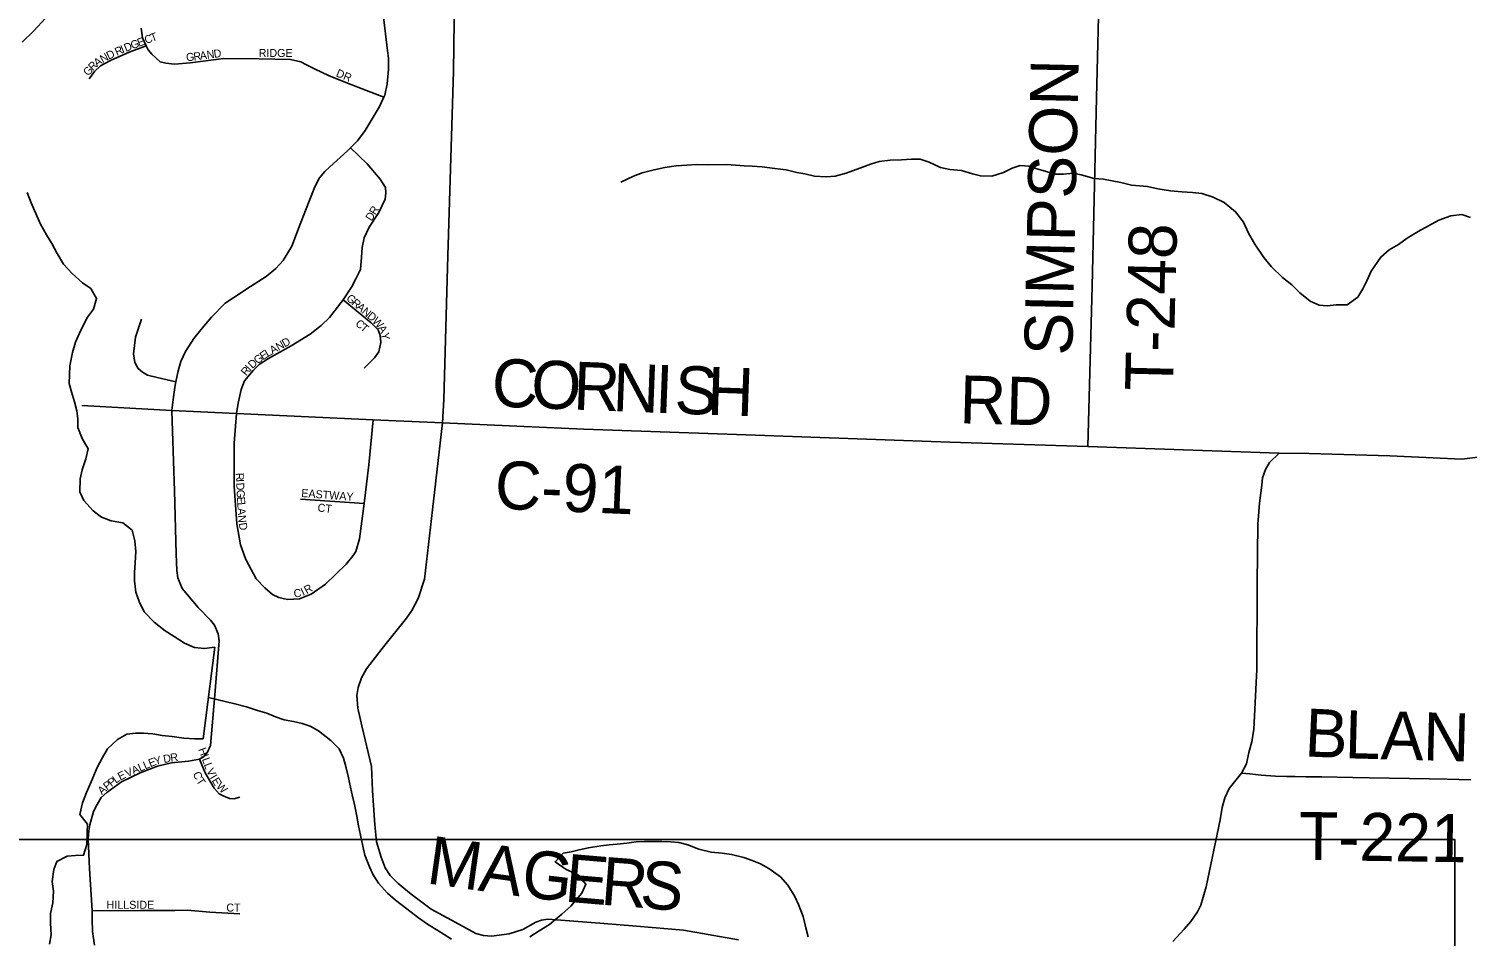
# Model space of a CAD drawing. Extents: x 1759416 to 2214760, y 252598 to 1116833.
# Drawn here: x 2011247 to 2020235, y 879811 to 885483 of the extents above; entities that cross this region are included whole.
import ezdxf

# ---------------------------------------------------------------- set-up
doc = ezdxf.new("R2010")
doc.units = 0
for name, color, linetype in [('GM_X_County_Road', 7, 'Continuous'), ('GM_X_County_Road_Text', 7, 'Continuous'), ('GM_X_County_Subdivision', 7, 'Continuous'), ('GM_X_County_Subdivision_Text', 7, 'Continuous'), ('GM_X_Major_Lake', 7, 'Continuous'), ('GM_X_Minor_River', 7, 'Continuous'), ('GM_X_Township_Road', 7, 'Continuous'), ('GM_X_Township_Road_Text', 7, 'Continuous'), ('GM_X_Township_Subdivision', 7, 'Continuous'), ('GM_X_Township_Subdivision_Text', 7, 'Continuous'), ('SC_Scratch1', 7, 'Continuous')]:
    doc.layers.add(name, color=color, linetype=linetype)

msp = doc.modelspace()

# ---------------------------------------------------------------- linework, layer by layer
at = {"layer": 'GM_X_County_Road'}
for points in [[(2013409.9, 880508.4), (2013409.8, 880509.6), (2013407.5, 880535.4), (2013395.7, 880721.7), (2013387.9, 880872), (2013328.1, 881126.5), (2013304.2, 881236.7), (2013296.3, 881314.8), (2013304.3, 881364.9), (2013326.4, 881425), (2013356.5, 881481), (2013454.6, 881609.2), (2013606.9, 881799.3), (2013641, 881847.4), (2013681.1, 881921.4), (2013719.2, 882041.6), (2013769.7, 882476.3), (2013832.3, 883019.1), (2013840.5, 883165.4), (2013865.4, 884062.9), (2013900.7, 885216.8), (2013909.3, 885843.9)], [(2012141.5, 883096.3), (2012544.1, 883078.3), (2013398.5, 883039.3), (2013832.3, 883019.1)], [(2013832.3, 883019.1), (2014715, 882979.1), (2015730.3, 882945), (2017002, 882898.3), (2017865.1, 882871.3), (2019061, 882830.6)], [(2018395.4, 879778.2), (2018465.5, 879854.2), (2018507.6, 879902.2), (2018549.7, 879962.3), (2018569.8, 880004.3), (2018603.9, 880118.5), (2018690.4, 880539.1), (2018704.5, 880615.2), (2018720.5, 880675.3), (2018746.6, 880733.3), (2018824.1, 880830.2), (2018856.7, 880887.4), (2018870.9, 880959.6), (2018889, 881025.7), (2018901.1, 881105.8), (2018919.5, 881478.4), (2018922, 882015.3), (2018926.4, 882386), (2018936.6, 882518.2), (2018952.7, 882630.4), (2018956.8, 882676.4), (2018974.8, 882728.5), (2018998.9, 882772.5), (2019061, 882830.6), (2019247.1, 882828.3), (2019751.3, 882813.7), (2020201.6, 882793.1), (2020317.6, 882807)], [(2015682, 879787.4), (2015337.9, 879847.9), (2015043.7, 879874.4), (2014815.6, 879892.6), (2014489.5, 879917.1), (2014451.4, 879911.1), (2014415.4, 879899.1), (2014333.3, 879853.1), (2014249.2, 879825.2), (2014139.1, 879811.3), (2014089.1, 879815.4), (2014041.1, 879827.4), (2013911.1, 879897.7), (2013761.1, 879980), (2013637.1, 880074.3), (2013555.2, 880140.5), (2013505.2, 880190.7), (2013473.2, 880238.8), (2013449.3, 880304.9), (2013419.4, 880401.1), (2013409.9, 880508.4)]]:
    msp.add_lwpolyline(points, dxfattribs=at)
at = {"layer": 'GM_X_County_Subdivision'}
msp.add_lwpolyline([(2013461.7, 885572.8), (2013484.9, 885380.5), (2013495.4, 885296.4), (2013493.8, 885228.3), (2013486.4, 885138.1), (2013472.8, 885067.8), (2013466.6, 885054.6), (2013437.2, 884991.5), (2013350, 884846.7), (2013300.4, 884782.3), (2013257.6, 884739), (2013238.7, 884719.8), (2013129.2, 884619), (2013097.4, 884590.8), (2013063.6, 884550.5), (2013033.9, 884494.2), (2012998.4, 884405.8), (2012943.2, 884261.2), (2012890, 884124.6), (2012836.5, 884034.2), (2012790.8, 883983.8), (2012731, 883933.3), (2012633.3, 883870.6), (2012527.6, 883803.9), (2012473.7, 883767.5), (2012388.2, 883680.8), (2012340.5, 883624.5), (2012278.9, 883546), (2012227.3, 883465.5), (2012197.7, 883403.2), (2012180, 883345), (2012166.6, 883275.8), (2012162.6, 883254.7), (2012151, 883182.5), (2012141.5, 883096.3), (2012143.9, 883030.2), (2012158.6, 882595.4), (2012169, 882200.8), (2012171.7, 882096.6), (2012178, 882050.5), (2012206.4, 881984.6), (2012305.3, 881864.9), (2012381.9, 881785.2), (2012408.1, 881755.3), (2012430.4, 881701.4), (2012436.7, 881657.3), (2012408.8, 881318.5), (2012382.7, 881003.7), (2012362.9, 880961.6), (2012339.1, 880931.3), (2012312.9, 880916.8), (2012245.1, 880904.8), (2012139.1, 880894.1), (2012051.1, 880873.6), (2011943.3, 880832.9), (2011827.5, 880776.1), (2011733.8, 880709.4), (2011699.9, 880677.1), (2011674.2, 880634.9), (2011652.4, 880590.7), (2011628.9, 880506.4), (2011623.1, 880470.3), (2011617.4, 880420.2), (2011626.6, 880231.9), (2011642.2, 879971.5), (2011644, 879916.3), (2011646.3, 879840.2), (2011657.6, 879755.1)], dxfattribs=at)
at = {"layer": 'GM_X_Major_Lake'}
for points in [[(2011205.5, 885397.8), (2011279.3, 885470.2), (2011351.1, 885548.6)], [(2012409.6, 881618.1), (2012345.5, 881609.9), (2012283.4, 881615.7), (2012219.2, 881641.5), (2012155, 881683.4), (2012098.8, 881719.3), (2012030.5, 881773.2), (2011968.1, 881839.1), (2011937.8, 881903.1), (2011915.6, 881961.2), (2011907.3, 882031.3), (2011907.1, 882083.4), (2011910.9, 882145.5), (2011916.6, 882215.7), (2011910.4, 882281.8), (2011894.1, 882347.9), (2011835.8, 882393.8), (2011761.7, 882407.5), (2011701.5, 882429.4), (2011649.3, 882469.3), (2011591, 882533.2), (2011566.7, 882589.2), (2011568.4, 882669.4), (2011580.2, 882725.6), (2011604, 882793.8), (2011617.8, 882858), (2011581.5, 882922), (2011553.2, 882990), (2011552.9, 883044.1), (2011546.8, 883094.2), (2011532.5, 883150.3), (2011514.3, 883212.3), (2011500, 883266.4), (2011501.8, 883320.5), (2011503.6, 883376.7), (2011519.3, 883458.9), (2011539.1, 883523.1), (2011572.9, 883599.3), (2011614.6, 883679.7), (2011652.5, 883729.9), (2011670.3, 883796.1), (2011634, 883858.1), (2011583.8, 883894), (2011517.4, 883951.9), (2011465.1, 884011.8), (2011424.8, 884077.8), (2011390.6, 884139.8), (2011358.3, 884193.8), (2011320, 884261.8), (2011297.8, 884313.9), (2011261.4, 884393.9), (2011237.1, 884460)], [(2012337.7, 881044.7), (2012409.6, 881618.1)], [(2011377.2, 879760.8), (2011387, 879819), (2011382.7, 879893.1), (2011382.5, 879953.2), (2011398.3, 880019.4), (2011402, 880091.6), (2011393.8, 880153.7), (2011403.5, 880227.8), (2011423.3, 880278), (2011487.3, 880310.3), (2011539.4, 880314.5), (2011589.4, 880316.7), (2011609.2, 880384.9), (2011612.9, 880461), (2011614.7, 880511.2), (2011566.4, 880571.1), (2011582.1, 880645.3), (2011607.9, 880709.5), (2011637.7, 880775.8), (2011673.4, 880866.1), (2011707.2, 880928.3), (2011739.1, 880982.5), (2011800.9, 881040.9), (2011858.9, 881073.1), (2011913, 881079.3), (2011963, 881079.5), (2012023.1, 881075.7), (2012081.2, 881065.9), (2012143.4, 881058.1), (2012215.5, 881048.3), (2012285.6, 881044.5), (2012337.7, 881044.7)]]:
    msp.add_lwpolyline(points, dxfattribs=at)
at = {"layer": 'GM_X_Minor_River'}
for points in [[(2016285.8, 884561.3), (2016229.7, 884557.1), (2016157.6, 884560.9), (2016095.5, 884576.7), (2016045.4, 884584.6), (2015979.2, 884600.4), (2015909.1, 884610.2), (2015828.9, 884619.9), (2015766.8, 884623.7), (2015716.8, 884625.5), (2015608.6, 884633.2), (2015486.4, 884632.8), (2015418.3, 884634.5), (2015358.2, 884630.3), (2015292.2, 884626.1), (2015222.1, 884615.8), (2015154.1, 884601.6), (2015080, 884581.3), (2015026, 884561.1), (2014946.1, 884524.7)], [(2020256.3, 884302.2), (2020202.1, 884322), (2020132.1, 884313.8), (2020058.1, 884285.5), (2019994.1, 884251.2), (2019928.2, 884214.9), (2019860.2, 884174.6), (2019806.3, 884134.3), (2019748.4, 884100), (2019694.5, 884055.8), (2019634.7, 883967.4), (2019606.9, 883907.2), (2019583.1, 883857), (2019551.2, 883804.8), (2019485.3, 883756.4), (2019417.2, 883756.2), (2019359.2, 883750), (2019309.1, 883755.9), (2019252.9, 883779.7), (2019188.6, 883831.6), (2019138.3, 883881.5), (2019080.1, 883927.4), (2019011.7, 883995.4), (2018963.5, 884053.3), (2018907.1, 884135.3), (2018868.7, 884205.3), (2018836.4, 884273.3), (2018788.1, 884339.3), (2018715.8, 884397.2), (2018647.6, 884431), (2018577.4, 884452.8), (2018519.3, 884458.7), (2018451.2, 884462.4), (2018381.1, 884470.2), (2018302.9, 884482), (2018236.8, 884495.8), (2018186.7, 884501.6), (2018136.6, 884505.5), (2018070.4, 884521.3), (2018016.3, 884533.1), (2017962.2, 884542.9), (2017904.1, 884546.8), (2017823.9, 884570.5), (2017769.8, 884580.4), (2017711.7, 884574.2), (2017655.7, 884574), (2017597.5, 884591.8), (2017545.4, 884607.7), (2017495.2, 884623.5), (2017441.1, 884627.4), (2017391.1, 884611.2), (2017337.2, 884584.9), (2017265.2, 884560.6), (2017193, 884562.4), (2017142.9, 884576.2), (2017074.8, 884596.1), (2017002.6, 884603.8), (2016944.5, 884615.7), (2016872.3, 884649.5), (2016816.1, 884667.3), (2016762, 884667.2), (2016700, 884662.9), (2016629.9, 884660.7), (2016559.8, 884652.4), (2016505.8, 884636.2), (2016439.8, 884612), (2016353.8, 884579.6), (2016285.8, 884561.3)], [(2012843.9, 881162.7), (2012787.8, 881182.5), (2012735.6, 881204.4), (2012675.5, 881222.2), (2012607.3, 881244), (2012535.1, 881263.8), (2012370, 881302.8)], [(2013888.6, 879791.4), (2013820.4, 879835.3), (2013738, 879887.1), (2013681.8, 879925), (2013609.5, 879980.9), (2013539.2, 880036.8), (2013489, 880080.7), (2013432.6, 880142.6), (2013398.4, 880194.6), (2013376.2, 880244.6), (2013347.9, 880316.7), (2013333.6, 880372.7), (2013319.3, 880442.8), (2013307.1, 880500.9), (2013296.9, 880561), (2013282.6, 880633.1), (2013268.3, 880695.2), (2013254, 880761.3), (2013243.8, 880811.3), (2013229.6, 880863.4), (2013213.4, 880923.4), (2013187.1, 880981.5), (2013134.8, 881033.4), (2013056.5, 881095.3), (2013006.3, 881123.2), (2012956.2, 881141), (2012902, 881152.8), (2012843.9, 881162.7)], [(2016117.7, 879807), (2016103.4, 879863.1), (2016085.1, 879933.2), (2016056.8, 880009.2), (2016034.6, 880059.3), (2015990.3, 880129.2), (2015944, 880181.2), (2015871.7, 880233.1), (2015819.5, 880262.9), (2015767.3, 880284.8), (2015715.2, 880302.7), (2015639, 880322.5), (2015578.9, 880330.3), (2015510.8, 880336), (2015434.6, 880355.8), (2015364.4, 880381.6), (2015308.3, 880395.5), (2015256.2, 880401.3), (2015202.1, 880403.1), (2015094, 880402.8), (2015041.9, 880400.6), (2014983.9, 880392.4), (2014923.8, 880386.2), (2014873.7, 880382), (2014821.7, 880375.8), (2014743.6, 880363.5), (2014685.6, 880351.3), (2014635.6, 880339.1), (2014585.5, 880328.9), (2014535.7, 880276.6), (2014605.9, 880228.8), (2014676.2, 880196.9), (2014728.5, 880137), (2014702.6, 880080.8), (2014634.9, 879998.4), (2014577, 879948.1), (2014501.1, 879883.7), (2014437.2, 879845.4), (2014377.2, 879807.1)]]:
    msp.add_lwpolyline(points, dxfattribs=at)
at = {"layer": 'GM_X_Township_Road'}
for points in [[(2017865.1, 882871.3), (2017890.9, 883873.3), (2017917.7, 885051.7), (2017956.4, 886574.9), (2017989.9, 888044.9)], [(2011579.6, 883127.2), (2011692, 883121.1), (2011692, 883121.1)], [(2011692, 883121.1), (2012141.5, 883096.3)], [(2018824.1, 880830.2), (2018876.3, 880825.2), (2018948, 880818.4), (2019036.2, 880811.9), (2019108.2, 880809.3), (2019160.6, 880808.5), (2019226, 880807.7), (2019327.4, 880807.1), (2019520.2, 880803.4), (2019624.9, 880800.4), (2019998.5, 880794.5), (2020110, 880792.5), (2020257.5, 880787.6)]]:
    msp.add_lwpolyline(points, dxfattribs=at)
at = {"layer": 'GM_X_Township_Subdivision'}
for points in [[(2013466.6, 885054.6), (2013357.5, 885095.9), (2013237.7, 885143), (2013120, 885190.1), (2013036.3, 885230.9), (2012982.4, 885257.4), (2012946.5, 885275.7), (2012882.6, 885290.3), (2012686.5, 885293.9), (2012466.3, 885295.8), (2012255.9, 885269.5), (2012157.7, 885262.3), (2012103.7, 885266.7), (2012067.7, 885275.1), (2012016.1, 885323.6), (2011992.3, 885351.8), (2011980.4, 885376.8), (2011956.9, 885426.3), (2011949.4, 885486.5)], [(2011624.5, 885168.6), (2011656.9, 885216.4), (2011695.2, 885250.1), (2011757.5, 885283.7), (2011874.1, 885336.8), (2011980.4, 885376.8)], [(2012544.1, 883078.3), (2012554.7, 883143.1), (2012573.4, 883227.1), (2012595.8, 883281), (2012648.4, 883346.7), (2012686.8, 883384.5), (2012745.1, 883422), (2012885.9, 883501), (2013004.6, 883574.1), (2013073.1, 883627.6), (2013125.6, 883677.3), (2013210.6, 883788.8), (2013263.3, 883868.5), (2013291.7, 883920.3), (2013320.2, 883978.2), (2013326.8, 884054.3), (2013329.3, 884114.4), (2013341.9, 884176.4), (2013374.4, 884242.2), (2013435.2, 884333.9), (2013474, 884417.7), (2013478.3, 884457.7), (2013476.6, 884489.8), (2013443, 884542.2), (2013361.7, 884639), (2013257.6, 884739)], [(2013343.2, 883360.9), (2013407.8, 883426.5), (2013434.1, 883464.3), (2013446.6, 883522.3), (2013442.9, 883564.4), (2013429.2, 883600.6), (2013385.5, 883645.1), (2013210.6, 883788.8)], [(2012166.6, 883275.8), (2012049.5, 883303.6), (2011989.6, 883318.1), (2011957.7, 883336.5), (2011929.9, 883358.7), (2011910.1, 883397), (2011900.6, 883451.2), (2011913.5, 883555.2), (2011952.4, 883667.1)], [(2012544.1, 883078.3), (2012530.6, 882892.9), (2012530.4, 882624.4), (2012546.4, 882387.8), (2012569.4, 882257.4), (2012602.7, 882164.9), (2012667.7, 882044.2), (2012721.3, 881987.6), (2012771, 881947.2), (2012808.9, 881926.8), (2012862.8, 881916.3), (2012939, 881919.7), (2013011.3, 881949.1), (2013101.8, 882010.5), (2013231, 882135.6), (2013273.5, 882189.4), (2013291.7, 882215.3), (2013314.4, 882295.2), (2013342.2, 882515.4), (2013372.2, 882757.6), (2013398.5, 883039.3)], [(2012944.1, 882542.8), (2013342.2, 882515.4)], [(2012566.9, 880680.2), (2012528.9, 880670), (2012500.9, 880671.8), (2012460.7, 880687.6), (2012436.6, 880701.5), (2012406.3, 880735.4), (2012349.7, 880831.2), (2012312.9, 880916.8)], [(2011642.2, 879971.5), (2011758.4, 879970.1), (2011944.6, 879971.2), (2012158.8, 879972.5), (2012238.9, 879972.9), (2012379.1, 879961.8), (2012565.4, 879950.8)]]:
    msp.add_lwpolyline(points, dxfattribs=at)
at = {"layer": 'SC_Scratch1'}
msp.add_lwpolyline([(1984253.2, 880416.3), (2020157.2, 880416.3), (2020157.2, 844512.3), (1984253.2, 844512.3)], close=True, dxfattribs=at)

# ---------------------------------------------------------------- texts
at = {"layer": 'GM_X_County_Road_Text'}
for s, rotation, p in [('C', 357.79035, (2014136, 883122.4)), ('O', 357.78944, (2014382.2, 883112.9)), ('R', 357.79035, (2014646, 883102.7)), ('N', 357.78944, (2014892.2, 883093.2)), ('I', 357.7905, (2015156, 883083.1)), ('S', 357.78896, (2015279.1, 883078.3)), ('H', 357.94893, (2015482.3, 883070.5)), ('RD', 358.51749, (2017060.5, 883016.8)), ('C-91', 357.60581, (2014154.9, 882483.8)), ('M', 351.95761, (2013725.6, 880142.5)), ('A', 352.03801, (2014048.5, 880096.9)), ('G', 353.3518, (2014317.4, 880059.4)), ('E', 355.13416, (2014589.7, 880027.8)), ('R', 355.54038, (2014815.6, 880008.6)), ('S', 355.07142, (2015060.6, 879989.5))]:
    msp.add_text(s, height=300, rotation=rotation, dxfattribs=at).set_placement(p)
at = {"layer": 'GM_X_County_Subdivision_Text'}
for s, rotation, p in [('E', 22.42025, (2012006.7, 880866)), ('Y', 15.08066, (2012037.7, 880878.9)), ('D', 10.6841, (2012092.1, 880892.8)), ('R', 7.9927, (2012134.7, 880900.8)), ('E', 26.87046, (2011818.6, 880782.6)), ('V', 23.25024, (2011861.3, 880803.5)), ('A', 23.25024, (2011901.8, 880820.9)), ('L', 23.25239, (2011942.2, 880838.3)), ('L', 23.22729, (2011974.5, 880852.2)), ('A', 42.23252, (2011704.4, 880691.8)), ('P', 38.24163, (2011736.3, 880720.8)), ('P', 36.99557, (2011763.7, 880742.4)), ('L', 35.09944, (2011791.4, 880763.4))]:
    msp.add_text(s, height=50, rotation=rotation, dxfattribs=at).set_placement(p)
at = {"layer": 'GM_X_Township_Road_Text'}
for s, rotation, p in [('SIMPSON', 88.73058, (2017766.7, 883438.2)), ('T-248', 88.59675, (2018396.4, 883216.1)), ('B', 357.30599, (2019215, 880935.3)), ('L', 358.45937, (2019467.7, 880923.4)), ('A', 358.5043, (2019692.3, 880917.4)), ('N', 358.50263, (2019956.2, 880910.5)), ('T-221', 359.15807, (2019181.4, 880288.2))]:
    msp.add_text(s, height=300, rotation=rotation, dxfattribs=at).set_placement(p)
at = {"layer": 'GM_X_Township_Subdivision_Text'}
for s, rotation, p in [('E', 20.54325, (2011935.2, 885369.3)), ('C', 20.5629, (2011980.6, 885386.3)), ('T', 20.54325, (2012017.6, 885400.2)), ('N', 29.3518, (2011708.7, 885267.3)), ('D', 25.39192, (2011746.2, 885288.5)), ('R', 23.90331, (2011797.7, 885312.7)), ('I', 23.88707, (2011833.9, 885328.7)), ('D', 22.02465, (2011853.6, 885337.4)), ('G', 20.64047, (2011894.1, 885353.8)), ('G', 3.84896, (2012231.6, 885279.9)), ('R', 7.40272, (2012278.9, 885283.1)), ('A', 7.76914, (2012318.5, 885288.3)), ('N', 7.76221, (2012362.1, 885294.2)), ('D', 7.7821, (2012405.7, 885300.2)), ('RIDGE', 0.00001, (2012683.9, 885306.2)), ('G', 51.17972, (2011620.3, 885183.6)), ('R', 44.10697, (2011646.8, 885216.7)), ('A', 34.79328, (2011673.6, 885242.9)), ('DR', 337.62245, (2013162.7, 885186.7)), ('R', 59.21274, (2013413.3, 884315.2)), ('D', 57.55898, (2013388.8, 884276.8)), ('G', 319.82782, (2013226.7, 883790.5)), ('R', 319.83067, (2013260.3, 883762.1)), ('A', 319.82782, (2013290.6, 883736.5)), ('N', 319.82782, (2013324.2, 883708.2)), ('D', 319.37738, (2013357.7, 883679.9)), ('C', 317.81781, (2013283.6, 883634.1)), ('T', 319.68976, (2013314.3, 883606.4)), ('W', 312.39582, (2013390, 883652.3)), ('A', 300.53647, (2013426.9, 883612.3)), ('N', 29.57681, (2012807.7, 883468.5)), ('D', 29.60138, (2012846, 883490.3)), ('Y', 278.90901, (2013447.6, 883579)), ('G', 36.6557, (2012676, 883383.9)), ('E', 33.72038, (2012710.7, 883409.7)), ('L', 30.57495, (2012739.4, 883428.9)), ('A', 29.75301, (2012769.5, 883446.7)), ('R', 50.52092, (2012606, 883309.4)), ('I', 48.68242, (2012630.9, 883339.6)), ('D', 42.32515, (2012644.4, 883355.1)), ('R', 273.20678, (2012539.3, 882705.7)), ('I', 273.23783, (2012541.5, 882666.2)), ('D', 273.215, (2012542.8, 882644.2)), ('G', 273.215, (2012545.2, 882600.3)), ('E', 273.22971, (2012547.7, 882556.3)), ('EASTWAY', 355.7938, (2012948.6, 882556.2)), ('L', 273.2253, (2012549.7, 882521.2)), ('A', 273.215, (2012551.7, 882486.1)), ('CT', 353.66381, (2013049.4, 882466.3)), ('N', 274.07806, (2012554.2, 882441.3)), ('D', 281.00597, (2012558.2, 882390.9)), ('R', 28.99756, (2012983.9, 881948.1)), ('C', 7.91718, (2012905.7, 881927.2)), ('I', 24.63199, (2012960.2, 881937.1)), ('H', 290.08022, (2012305.5, 880979.2)), ('I', 290.08615, (2012320.6, 880937.9)), ('L', 290.08778, (2012328.2, 880917.2)), ('C', 291.48569, (2012271.3, 880828.2)), ('L', 290.28809, (2012340.3, 880884)), ('V', 297.23094, (2012355.2, 880845)), ('T', 302.95871, (2012290.8, 880781.7)), ('I', 300.93959, (2012377, 880802.9)), ('E', 301.38294, (2012388.5, 880783.6)), ('W', 314.65168, (2012414.5, 880743.8)), ('HILLSIDE', 0.00001, (2011733.5, 879982.2)), ('CT', 0.00001, (2012481.5, 879964.6))]:
    msp.add_text(s, height=50, rotation=rotation, dxfattribs=at).set_placement(p)

doc.saveas('drawing.dxf')
